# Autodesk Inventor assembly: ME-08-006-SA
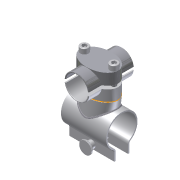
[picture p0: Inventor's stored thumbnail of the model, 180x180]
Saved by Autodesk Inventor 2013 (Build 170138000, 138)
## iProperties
Shininess: 64.0
Length Units: 11269
Angle Units: 11279
Time Units: 11290
Mass Units: 11283
Length Display Precision: 3
Angle Display Precision: 2
Compacted: True
Created: 2002-10
Part Number: ME-08-006-SA
Document SubType Name: Assembly
Designer: roithn
Density: 0.0
Volumn: 0.0
Area: 0.0
PropertySet Name: Model Information
Control State: 0
Master: False
Checked Out: False
Author: roithn
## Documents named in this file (4)
- C:\Webworld\Webworld2014\ATC2013\Assemblies\ATC-Baby Carriage\CLAMPDAMPER\ME-08-006-SA.iam
- C:\Webworld\Webworld2014\ATC2013\Assemblies\ATC-Baby Carriage\CLAMPDAMPER\Clamp_top.ipt
- C:\Webworld\Webworld2014\ATC2013\Assemblies\ATC-Baby Carriage\CLAMPDAMPER\Clamp_welded.iam
- C:\Webworld\Webworld2014\ATC2013\Assemblies\ATC-Baby Carriage\CLAMPDAMPER\local.ISO.13.620.1.ipt
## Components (4 placed, 3 different names)
1. Clamp_top:1 — Insert:1, Insert:2
2. Clamp_welded:1 [sub-assembly]
3. ISO 4762  (Regular Thread) M6 x 25:1 — Insert:1
4. ISO 4762  (Regular Thread) M6 x 25:2 — Insert:2
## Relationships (2: Insert 2)
- Insert:1: Clamp_top:1 ↔ ISO 4762  (Regular Thread) M6 x 25:1
- Insert:2: Clamp_top:1 ↔ ISO 4762  (Regular Thread) M6 x 25:2
